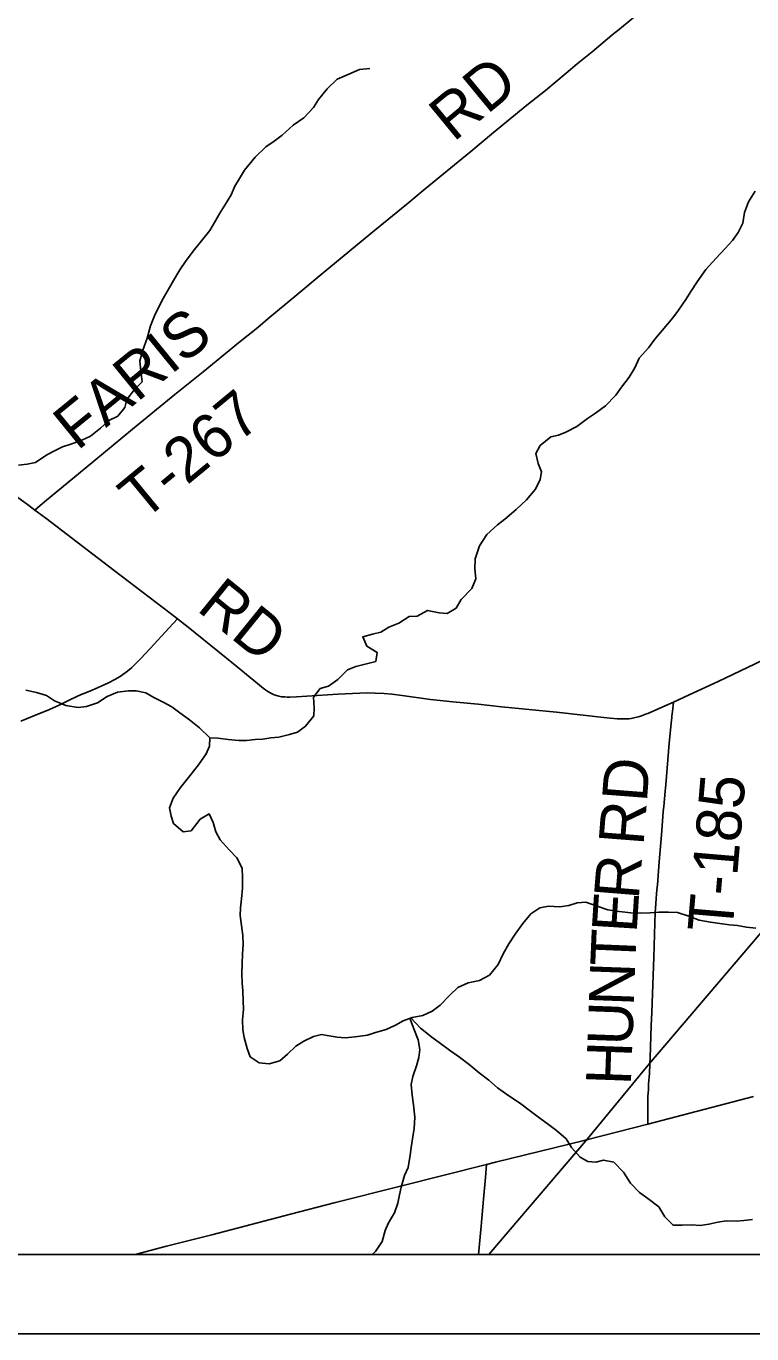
# Model space of a CAD drawing. Extents: x 0 to 34, y 0 to 22.
# Drawn here: x 4.922 to 5.838, y 14 to 15.651 of the extents above; entities that cross this region are included whole.
import ezdxf

# ---------------------------------------------------------------- set-up
doc = ezdxf.new("R2010")
doc.units = 0
for name, color, linetype in [('GM_X_County_Road', 7, 'Continuous'), ('GM_X_County_Road_Text', 7, 'Continuous'), ('GM_X_Minor_River', 7, 'Continuous'), ('GM_X_State_Route', 7, 'Continuous'), ('GM_X_Township_Road', 7, 'Continuous'), ('GM_X_Township_Road_Text', 7, 'Continuous'), ('SH_Data', 7, 'Continuous')]:
    doc.layers.add(name, color=color, linetype=linetype)

msp = doc.modelspace()

# ---------------------------------------------------------------- linework, layer by layer
at = {"layer": 'GM_X_County_Road'}
for points in [[(4.878, 15.0796), (4.9253, 15.0455), (4.9331, 15.0397)], [(4.9331, 15.0397), (4.9467, 15.0295), (5.0332, 14.9635), (5.0771, 14.9299), (5.1038, 14.9096), (5.1131, 14.9023)], [(5.7389, 14.7973), (5.7589, 14.8065), (5.7955, 14.8235), (5.842, 14.8458), (5.8755, 14.862), (5.8984, 14.8732), (5.9168, 14.8822), (5.9548, 14.9006), (6.0128, 14.9292), (6.0575, 14.951), (6.087, 14.9655), (6.1034, 14.9732), (6.1115, 14.9766), (6.1136, 14.9773), (6.1157, 14.9779), (6.1176, 14.9784), (6.12, 14.9788), (6.1233, 14.979), (6.1268, 14.9789)], [(5.1131, 14.9023), (5.1263, 14.892), (5.1838, 14.8455), (5.2092, 14.8245), (5.2213, 14.8148), (5.2258, 14.8115), (5.2299, 14.8089), (5.2326, 14.8076), (5.2352, 14.8065), (5.2379, 14.8055), (5.2408, 14.8048), (5.2444, 14.8042), (5.2485, 14.8038), (5.2514, 14.8037), (5.2546, 14.8036), (5.2632, 14.8039), (5.3153, 14.8074), (5.3433, 14.8087), (5.3526, 14.8089), (5.3626, 14.8087), (5.3738, 14.8081), (5.3837, 14.8072), (5.3967, 14.8056), (5.4323, 14.8008), (5.4607, 14.7978), (5.4923, 14.7946), (5.5219, 14.7915), (5.5912, 14.7845), (5.6548, 14.7776), (5.6678, 14.7764), (5.6733, 14.7761), (5.6762, 14.7761), (5.6795, 14.7762), (5.6826, 14.7764), (5.6857, 14.7768), (5.6891, 14.7774), (5.6928, 14.7783), (5.6962, 14.7793), (5.6998, 14.7804), (5.7039, 14.782), (5.7066, 14.783), (5.7096, 14.7843), (5.7295, 14.7931), (5.7389, 14.7973)], [(5.493, 14.1), (5.4963, 14.136), (5.4993, 14.1701), (5.5016, 14.1973), (5.5031, 14.2136)]]:
    msp.add_lwpolyline(points, dxfattribs=at)
at = {"layer": 'GM_X_Minor_River'}
for points in [[(4.9122, 15.0964), (4.9233, 15.0977), (4.9336, 15.0999), (4.9481, 15.1095), (4.9584, 15.1151), (4.968, 15.1195), (4.9783, 15.1228), (4.9924, 15.128), (5.0031, 15.1328), (5.0158, 15.1432), (5.0262, 15.1526), (5.0376, 15.1581), (5.0465, 15.169), (5.0489, 15.1792), (5.0586, 15.192), (5.0682, 15.2014), (5.0665, 15.2151), (5.0656, 15.228), (5.0692, 15.2416), (5.0747, 15.2567), (5.0791, 15.2722), (5.0838, 15.2847), (5.0897, 15.2971), (5.0947, 15.3069), (5.1079, 15.3295), (5.1161, 15.3431), (5.1231, 15.3533), (5.1327, 15.3664), (5.1536, 15.3927), (5.1598, 15.4025), (5.1664, 15.4146), (5.175, 15.4278), (5.1808, 15.4376), (5.1855, 15.4485), (5.1913, 15.4583), (5.1976, 15.4688), (5.2111, 15.485), (5.2245, 15.4981), (5.2349, 15.5052), (5.2449, 15.513), (5.2591, 15.5254), (5.2725, 15.5347), (5.2845, 15.5478), (5.2911, 15.558), (5.3019, 15.5715), (5.3146, 15.5835), (5.3291, 15.5901), (5.3425, 15.596), (5.3558, 15.597)], [(5.1537, 14.7523), (5.164, 14.7518), (5.1769, 14.7501), (5.1902, 14.7488), (5.2, 14.7491), (5.2111, 14.7501), (5.2206, 14.7507), (5.2308, 14.7521), (5.2407, 14.7531), (5.2545, 14.7563), (5.2644, 14.7596), (5.2747, 14.7671), (5.2852, 14.7799), (5.2853, 14.7901), (5.2847, 14.8034), (5.2932, 14.8147), (5.3035, 14.8176), (5.3154, 14.8258), (5.3277, 14.8382), (5.338, 14.8422), (5.3632, 14.8487), (5.3649, 14.8601), (5.352, 14.8678), (5.3469, 14.8797), (5.3591, 14.8833), (5.3698, 14.8858), (5.3797, 14.8921), (5.3923, 14.8969), (5.4053, 14.9055), (5.4156, 14.9057), (5.4286, 14.9131), (5.4434, 14.9099), (5.4533, 14.909), (5.4647, 14.9161), (5.471, 14.927), (5.4844, 14.9409), (5.4895, 14.953), (5.4882, 14.9659), (5.4887, 14.978), (5.4943, 14.9947), (5.5036, 15.009), (5.5167, 15.021), (5.5263, 15.0284), (5.5405, 15.0404), (5.5536, 15.0527), (5.5648, 15.0663), (5.5706, 15.0783), (5.5723, 15.0882), (5.5682, 15.0985), (5.5654, 15.111), (5.5708, 15.1212), (5.5843, 15.1321), (5.5938, 15.1342), (5.6033, 15.1379), (5.6171, 15.1453), (5.6305, 15.1554), (5.6405, 15.1621), (5.6531, 15.1714), (5.6662, 15.1849), (5.6736, 15.1947), (5.6833, 15.2075), (5.6903, 15.2191), (5.6957, 15.2316), (5.7077, 15.2443), (5.7154, 15.2553), (5.7247, 15.2665), (5.7382, 15.2823), (5.7455, 15.2921), (5.7548, 15.3056), (5.7611, 15.3154), (5.7688, 15.3278), (5.78, 15.3432), (5.7924, 15.3571), (5.8043, 15.3699), (5.8136, 15.38), (5.8206, 15.3902), (5.8264, 15.4019), (5.8285, 15.4155), (5.8336, 15.4287), (5.8421, 15.4423)], [(4.9217, 14.8123), (4.935, 14.8095), (4.9475, 14.8055), (4.9576, 14.7989), (4.972, 14.793), (4.9875, 14.7906), (4.9982, 14.7919), (5.0119, 14.7963), (5.0242, 14.8045), (5.0372, 14.81), (5.0512, 14.8114), (5.0607, 14.8116), (5.0732, 14.8092), (5.083, 14.803), (5.0958, 14.7967), (5.106, 14.7913), (5.1158, 14.784), (5.1282, 14.7751), (5.1406, 14.765), (5.1537, 14.7523), (5.1532, 14.7417), (5.1493, 14.7319), (5.1396, 14.718), (5.1284, 14.7041), (5.1168, 14.6894), (5.1075, 14.6763), (5.1028, 14.6638), (5.1049, 14.6535), (5.1079, 14.644), (5.1203, 14.6336), (5.1301, 14.635), (5.1414, 14.6496), (5.1528, 14.6563), (5.158, 14.6456), (5.1613, 14.6338), (5.1668, 14.6235), (5.1784, 14.6108), (5.1878, 14.6008), (5.1948, 14.5878), (5.1951, 14.576), (5.1949, 14.5624), (5.1936, 14.5491), (5.1923, 14.5377), (5.1921, 14.5279), (5.1956, 14.5028), (5.1958, 14.4918), (5.1949, 14.4792), (5.1944, 14.4675), (5.1942, 14.4542), (5.1944, 14.4428), (5.1954, 14.4333), (5.196, 14.4204), (5.1963, 14.4098), (5.1949, 14.3965), (5.1955, 14.3836), (5.1973, 14.3741), (5.2009, 14.3603), (5.2046, 14.3497), (5.2159, 14.3419), (5.2288, 14.341), (5.2421, 14.3446), (5.2517, 14.3532), (5.2625, 14.3633), (5.2725, 14.3693), (5.2847, 14.3752), (5.2946, 14.3777), (5.3044, 14.3761), (5.3147, 14.3744), (5.3245, 14.3735), (5.3371, 14.3749), (5.3527, 14.377), (5.363, 14.3803), (5.3763, 14.3843), (5.3882, 14.3894), (5.3978, 14.395), (5.4092, 14.3994), (5.4225, 14.4019), (5.4344, 14.4071), (5.4447, 14.4149), (5.4567, 14.4276), (5.4667, 14.437), (5.4797, 14.4429), (5.4942, 14.4458), (5.5068, 14.4528), (5.5176, 14.466), (5.5242, 14.4795), (5.5312, 14.4924), (5.539, 14.5044), (5.5487, 14.5179), (5.5591, 14.53), (5.5702, 14.5378), (5.5813, 14.5399), (5.5957, 14.539), (5.6071, 14.5407), (5.6174, 14.544), (5.6284, 14.545), (5.6413, 14.5403), (5.656, 14.5351), (5.6704, 14.5331)], [(5.6704, 14.5331), (5.6852, 14.5314), (5.6974, 14.5308), (5.7091, 14.5314), (5.7205, 14.5324), (5.7327, 14.5323), (5.7441, 14.5317), (5.7573, 14.5274), (5.7713, 14.5223), (5.7857, 14.5194), (5.7975, 14.5181), (5.8096, 14.5161), (5.8198, 14.5152), (5.8312, 14.5131), (5.843, 14.5119)], [(5.4063, 14.3983), (5.4113, 14.385), (5.4168, 14.3712), (5.4189, 14.3587), (5.4177, 14.3488), (5.4145, 14.3382), (5.4101, 14.3246), (5.4081, 14.3148), (5.409, 14.3011), (5.4108, 14.2889), (5.4125, 14.2733), (5.4119, 14.2593), (5.4098, 14.246), (5.4078, 14.2351), (5.4065, 14.2256), (5.404, 14.21), (5.3997, 14.1999), (5.3953, 14.1851), (5.3933, 14.1753), (5.3909, 14.165), (5.3869, 14.1529), (5.3792, 14.1401), (5.3749, 14.1303), (5.3713, 14.1167), (5.3627, 14.1039), (5.3586, 14.1)], [(5.4077, 14.3988), (5.4197, 14.386), (5.4339, 14.3744), (5.4449, 14.3663), (5.4565, 14.3582), (5.4689, 14.3493), (5.4813, 14.34), (5.4937, 14.3296), (5.5058, 14.32), (5.517, 14.3103), (5.531, 14.3003), (5.5445, 14.2914), (5.5584, 14.2809), (5.5705, 14.2724), (5.5814, 14.2643), (5.5915, 14.2566), (5.6035, 14.2462), (5.6102, 14.2351), (5.6211, 14.2232), (5.6309, 14.2177), (5.6411, 14.2168), (5.6507, 14.2194), (5.6639, 14.2166), (5.6759, 14.2039), (5.6848, 14.1901), (5.6961, 14.1782), (5.7066, 14.1708), (5.7205, 14.1604), (5.7283, 14.1478), (5.7385, 14.137), (5.7499, 14.1372), (5.7624, 14.1375), (5.7726, 14.1369), (5.7837, 14.1383), (5.7951, 14.1408), (5.8054, 14.1426), (5.8183, 14.1424), (5.8278, 14.1431), (5.8388, 14.1444)]]:
    msp.add_lwpolyline(points, dxfattribs=at)
at = {"layer": 'GM_X_State_Route'}
for points in [[(5.6309, 14.2454), (5.7065, 14.2645), (5.8402, 14.2995)], [(5.0596, 14.1), (5.0991, 14.1105), (5.1563, 14.1251), (5.2556, 14.1509), (5.3108, 14.1654), (5.3946, 14.1864), (5.5031, 14.2136), (5.5145, 14.2165), (5.6261, 14.2442), (5.6309, 14.2454)]]:
    msp.add_lwpolyline(points, dxfattribs=at)
at = {"layer": 'GM_X_Township_Road'}
for points in [[(3.7277, 16.7873), (3.6691, 16.5264), (3.3385, 15.3189), (3.2153, 14.8228), (3.0598, 14.2522), (3.3693, 14.1947), (3.882, 14.1), (5.5061, 14.1), (5.6307, 14.246), (5.7089, 14.3412), (6.2381, 14.9624), (6.7874, 15.6255), (6.8121, 15.6375), (7.6646, 16.0363), (8.8399, 16.5839), (8.8447, 16.5834), (8.8816, 16.5789), (8.8995, 16.5764), (8.9, 16.5763), (8.9, 19.1426)], [(4.9331, 15.0397), (4.9398, 15.0454), (4.9478, 15.0523), (4.9809, 15.0796), (5.0072, 15.1014), (5.0562, 15.1417), (5.1095, 15.1854), (5.1453, 15.2143), (5.1901, 15.2507), (5.2143, 15.2702), (5.2272, 15.281), (5.2634, 15.3114), (5.2945, 15.3371), (5.3572, 15.389), (5.3842, 15.411), (5.4025, 15.4259), (5.4254, 15.445), (5.4672, 15.4793), (5.4831, 15.4923), (5.5118, 15.5161), (5.5541, 15.5507), (5.5774, 15.5694), (5.6036, 15.5913), (5.6175, 15.6028), (5.6363, 15.6181), (5.6614, 15.639), (5.6654, 15.6423), (5.6689, 15.6452), (5.6904, 15.6628)], [(4.9151, 14.7733), (4.9347, 14.7812), (4.9484, 14.7868), (4.9552, 14.7898), (4.9643, 14.7941), (4.971, 14.7972), (4.9778, 14.8005), (4.985, 14.8039), (4.9915, 14.8068), (4.9981, 14.8096), (5.0051, 14.8125), (5.0165, 14.8173), (5.0211, 14.8194), (5.026, 14.8217), (5.0337, 14.8257), (5.0406, 14.8297), (5.0439, 14.832), (5.0482, 14.835), (5.0519, 14.8381), (5.0553, 14.8409), (5.0589, 14.8445), (5.0631, 14.8488), (5.0666, 14.8525), (5.0783, 14.8652), (5.1025, 14.891), (5.1131, 14.9023)], [(5.7091, 14.3407), (5.7095, 14.3489), (5.7109, 14.3887), (5.7117, 14.406), (5.7141, 14.4755), (5.7153, 14.5184), (5.716, 14.532), (5.7168, 14.5429), (5.7173, 14.5499), (5.7177, 14.5551), (5.7181, 14.5605), (5.7187, 14.5669), (5.7211, 14.5958), (5.7239, 14.6298), (5.7262, 14.6587), (5.7265, 14.6626), (5.7268, 14.6655), (5.7285, 14.685), (5.7289, 14.6892), (5.7292, 14.693), (5.7338, 14.7455), (5.7366, 14.7744), (5.7369, 14.7777), (5.7371, 14.7797), (5.7377, 14.7854), (5.7389, 14.7973)], [(5.7073, 14.3085), (5.7077, 14.3153), (5.7086, 14.3285), (5.7091, 14.3407)], [(5.7065, 14.2645), (5.7065, 14.2739), (5.7067, 14.2962), (5.7068, 14.3001), (5.707, 14.3037), (5.7073, 14.3085)]]:
    msp.add_lwpolyline(points, dxfattribs=at)
msp.add_lwpolyline([(5.5061, 14.1), (8.9, 14.1), (8.9, 16.5763), (8.8995, 16.5764), (8.8816, 16.5789), (8.8447, 16.5834), (8.8399, 16.5839), (7.6646, 16.0363), (6.8121, 15.6375), (6.7874, 15.6255), (6.2381, 14.9624), (5.7089, 14.3412), (5.6307, 14.246)], close=True, dxfattribs=at)
at = {"layer": 'SH_Data'}
for p, q in [((2.1, 14.1), (8.9, 14.1)), ((2, 14), (9, 14))]:
    msp.add_line(p, q, dxfattribs=at)

# ---------------------------------------------------------------- texts
at = {"layer": 'GM_X_County_Road_Text'}
msp.add_text('RD', height=0.05682, rotation=320.9531, dxfattribs=at).set_placement((5.1358, 14.9139))
at = {"layer": 'GM_X_Township_Road_Text'}
for s, height, rotation, p in [('RD', 0.05682, 39.4966, (5.4613, 15.5034)), ('FARIS', 0.05682, 39.187, (4.9866, 15.1138)), ('T-267', 0.05682, 39.5238, (5.0696, 15.0249)), ('RD', 0.05682, 85.5634, (5.7011, 14.6155)), ('T-185', 0.05682, 85.1474, (5.8134, 14.5055)), ('R', 0.0568, 85.3699, (5.6951, 14.5473)), ('E', 0.0568, 86.3721, (5.6925, 14.5052)), ('T', 0.0568, 87.5607, (5.6907, 14.463)), ('N', 0.0568, 87.9158, (5.6889, 14.4131)), ('U', 0.0568, 87.9275, (5.687, 14.3632)), ('H', 0.0568, 87.9231, (5.6852, 14.3132))]:
    msp.add_text(s, height=height, rotation=rotation, dxfattribs=at).set_placement(p)

doc.saveas('drawing.dxf')
